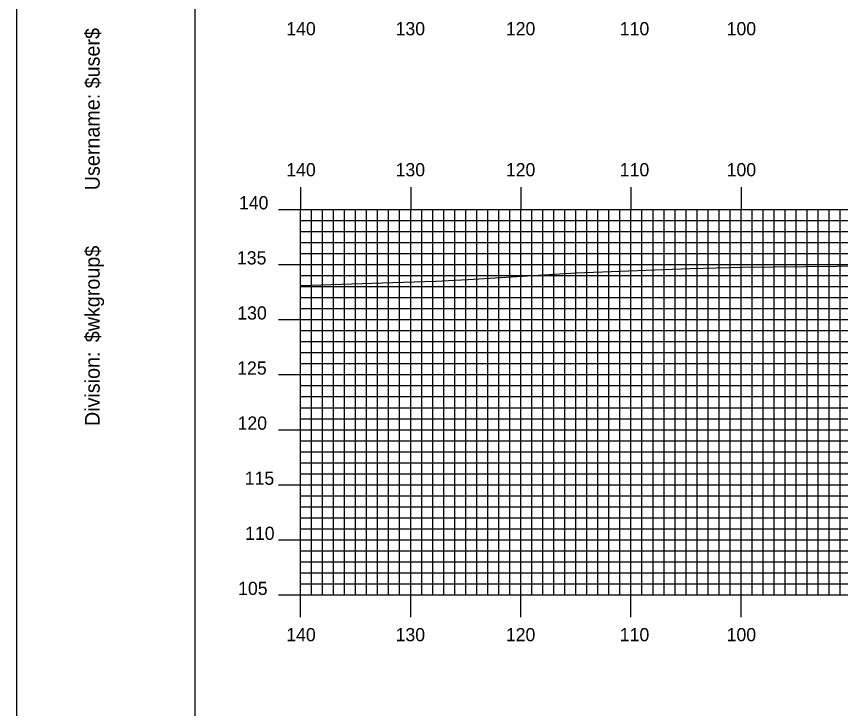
# Model space of a CAD drawing. Extents: x 1768087 to 1768430, y 442591 to 442811.
# Drawn here: x 1768087.2 to 1768162, y 442653.4 to 442716.2 of the extents above; entities that cross this region are included whole.
import ezdxf

# ---------------------------------------------------------------- set-up
doc = ezdxf.new("R2010")
doc.units = 0
for name, color, linetype in [('BORDER', 7, 'Continuous'), ('H_V ANNOTATION', 7, 'Continuous'), ('MAJOR', 7, 'Continuous'), ('MINOR', 7, 'Continuous'), ('PLOT BOUNDARY', 7, 'Continuous'), ('S_Roadway_Centerline', 7, 'Continuous')]:
    doc.layers.add(name, color=color, linetype=linetype)

msp = doc.modelspace()

# ---------------------------------------------------------------- linework, layer by layer
at = {"layer": 'BORDER'}
msp.add_lwpolyline([(1768103.363, 442596.665), (1768423.363, 442596.665), (1768423.363, 442806.665), (1768103.363, 442806.665)], close=True, dxfattribs=at)
at = {"layer": 'MAJOR'}
for p, q in [((1768112.963, 442700.669), (1768112.963, 442698.665)), ((1768122.963, 442700.669), (1768122.963, 442698.665)), ((1768132.963, 442700.669), (1768132.963, 442698.665)), ((1768142.963, 442700.669), (1768142.963, 442698.665)), ((1768152.963, 442700.669), (1768152.963, 442698.665)), ((1768110.959, 442698.665), (1768112.963, 442698.665)), ((1768112.963, 442698.665), (1768392.963, 442698.665)), ((1768112.963, 442663.665), (1768112.963, 442698.665)), ((1768112.963, 442663.665), (1768112.963, 442698.665)), ((1768112.963, 442698.665), (1768392.963, 442698.665)), ((1768122.963, 442663.665), (1768122.963, 442698.665)), ((1768132.963, 442663.665), (1768132.963, 442698.665)), ((1768142.963, 442663.665), (1768142.963, 442698.665)), ((1768152.963, 442663.665), (1768152.963, 442698.665)), ((1768110.959, 442693.665), (1768112.963, 442693.665)), ((1768112.963, 442693.665), (1768392.963, 442693.665)), ((1768110.959, 442688.665), (1768112.963, 442688.665)), ((1768112.963, 442688.665), (1768392.963, 442688.665)), ((1768110.959, 442683.665), (1768112.963, 442683.665)), ((1768112.963, 442683.665), (1768392.963, 442683.665)), ((1768110.959, 442678.665), (1768112.963, 442678.665)), ((1768112.963, 442678.665), (1768392.963, 442678.665)), ((1768110.959, 442673.665), (1768112.963, 442673.665)), ((1768112.963, 442673.665), (1768392.963, 442673.665)), ((1768110.959, 442668.665), (1768112.963, 442668.665)), ((1768112.963, 442668.665), (1768392.963, 442668.665)), ((1768110.959, 442663.665), (1768112.963, 442663.665)), ((1768112.963, 442663.665), (1768392.963, 442663.665)), ((1768112.963, 442663.665), (1768392.963, 442663.665)), ((1768112.963, 442661.661), (1768112.963, 442663.665)), ((1768122.963, 442661.661), (1768122.963, 442663.665)), ((1768132.963, 442661.661), (1768132.963, 442663.665)), ((1768142.963, 442661.661), (1768142.963, 442663.665)), ((1768152.963, 442661.661), (1768152.963, 442663.665))]:
    msp.add_line(p, q, dxfattribs=at)
at = {"layer": 'MINOR'}
for p, q in [((1768113.963, 442663.665), (1768113.963, 442698.665)), ((1768114.963, 442663.665), (1768114.963, 442698.665)), ((1768115.963, 442663.665), (1768115.963, 442698.665)), ((1768116.963, 442663.665), (1768116.963, 442698.665)), ((1768117.963, 442663.665), (1768117.963, 442698.665)), ((1768118.963, 442663.665), (1768118.963, 442698.665)), ((1768119.963, 442663.665), (1768119.963, 442698.665)), ((1768120.963, 442663.665), (1768120.963, 442698.665)), ((1768121.963, 442663.665), (1768121.963, 442698.665)), ((1768123.963, 442663.665), (1768123.963, 442698.665)), ((1768124.963, 442663.665), (1768124.963, 442698.665)), ((1768125.963, 442663.665), (1768125.963, 442698.665)), ((1768126.963, 442663.665), (1768126.963, 442698.665)), ((1768127.963, 442663.665), (1768127.963, 442698.665)), ((1768128.963, 442663.665), (1768128.963, 442698.665)), ((1768129.963, 442663.665), (1768129.963, 442698.665)), ((1768130.963, 442663.665), (1768130.963, 442698.665)), ((1768131.963, 442663.665), (1768131.963, 442698.665)), ((1768133.963, 442663.665), (1768133.963, 442698.665)), ((1768134.963, 442663.665), (1768134.963, 442698.665)), ((1768135.963, 442663.665), (1768135.963, 442698.665)), ((1768136.963, 442663.665), (1768136.963, 442698.665)), ((1768137.963, 442663.665), (1768137.963, 442698.665)), ((1768138.963, 442663.665), (1768138.963, 442698.665)), ((1768139.963, 442663.665), (1768139.963, 442698.665)), ((1768140.963, 442663.665), (1768140.963, 442698.665)), ((1768141.963, 442663.665), (1768141.963, 442698.665)), ((1768143.963, 442663.665), (1768143.963, 442698.665)), ((1768144.963, 442663.665), (1768144.963, 442698.665)), ((1768145.963, 442663.665), (1768145.963, 442698.665)), ((1768146.963, 442663.665), (1768146.963, 442698.665)), ((1768147.963, 442663.665), (1768147.963, 442698.665)), ((1768148.963, 442663.665), (1768148.963, 442698.665)), ((1768149.963, 442663.665), (1768149.963, 442698.665)), ((1768150.963, 442663.665), (1768150.963, 442698.665)), ((1768151.963, 442663.665), (1768151.963, 442698.665)), ((1768153.963, 442663.665), (1768153.963, 442698.665)), ((1768154.963, 442663.665), (1768154.963, 442698.665)), ((1768155.963, 442663.665), (1768155.963, 442698.665)), ((1768156.963, 442663.665), (1768156.963, 442698.665)), ((1768157.963, 442663.665), (1768157.963, 442698.665)), ((1768158.963, 442663.665), (1768158.963, 442698.665)), ((1768159.963, 442663.665), (1768159.963, 442698.665)), ((1768160.963, 442663.665), (1768160.963, 442698.665)), ((1768161.963, 442663.665), (1768161.963, 442698.665)), ((1768112.963, 442697.665), (1768392.963, 442697.665)), ((1768112.963, 442697.665), (1768114.967, 442697.665)), ((1768112.963, 442696.665), (1768392.963, 442696.665)), ((1768112.963, 442696.665), (1768114.967, 442696.665)), ((1768112.963, 442695.665), (1768392.963, 442695.665)), ((1768112.963, 442695.665), (1768114.967, 442695.665)), ((1768112.963, 442694.665), (1768392.963, 442694.665)), ((1768112.963, 442694.665), (1768114.967, 442694.665)), ((1768112.963, 442692.665), (1768392.963, 442692.665)), ((1768112.963, 442692.665), (1768114.967, 442692.665)), ((1768112.963, 442691.665), (1768392.963, 442691.665)), ((1768112.963, 442691.665), (1768114.967, 442691.665)), ((1768112.963, 442690.665), (1768392.963, 442690.665)), ((1768112.963, 442690.665), (1768114.967, 442690.665)), ((1768112.963, 442689.665), (1768392.963, 442689.665)), ((1768112.963, 442689.665), (1768114.967, 442689.665)), ((1768112.963, 442687.665), (1768392.963, 442687.665)), ((1768112.963, 442687.665), (1768114.967, 442687.665)), ((1768112.963, 442686.665), (1768392.963, 442686.665)), ((1768112.963, 442686.665), (1768114.967, 442686.665)), ((1768112.963, 442685.665), (1768392.963, 442685.665)), ((1768112.963, 442685.665), (1768114.967, 442685.665)), ((1768112.963, 442684.665), (1768392.963, 442684.665)), ((1768112.963, 442684.665), (1768114.967, 442684.665)), ((1768112.963, 442682.665), (1768392.963, 442682.665)), ((1768112.963, 442682.665), (1768114.967, 442682.665)), ((1768112.963, 442681.665), (1768392.963, 442681.665)), ((1768112.963, 442681.665), (1768114.967, 442681.665)), ((1768112.963, 442680.665), (1768392.963, 442680.665)), ((1768112.963, 442680.665), (1768114.967, 442680.665)), ((1768112.963, 442679.665), (1768392.963, 442679.665)), ((1768112.963, 442679.665), (1768114.967, 442679.665)), ((1768112.963, 442677.665), (1768392.963, 442677.665)), ((1768112.963, 442677.665), (1768114.967, 442677.665)), ((1768112.963, 442676.665), (1768392.963, 442676.665)), ((1768112.963, 442676.665), (1768114.967, 442676.665)), ((1768112.963, 442675.665), (1768392.963, 442675.665)), ((1768112.963, 442675.665), (1768114.967, 442675.665)), ((1768112.963, 442674.665), (1768392.963, 442674.665)), ((1768112.963, 442674.665), (1768114.967, 442674.665)), ((1768112.963, 442672.665), (1768392.963, 442672.665)), ((1768112.963, 442672.665), (1768114.967, 442672.665)), ((1768112.963, 442671.665), (1768392.963, 442671.665)), ((1768112.963, 442671.665), (1768114.967, 442671.665)), ((1768112.963, 442670.665), (1768392.963, 442670.665)), ((1768112.963, 442670.665), (1768114.967, 442670.665)), ((1768112.963, 442669.665), (1768392.963, 442669.665)), ((1768112.963, 442669.665), (1768114.967, 442669.665)), ((1768112.963, 442667.665), (1768392.963, 442667.665)), ((1768112.963, 442667.665), (1768114.967, 442667.665)), ((1768112.963, 442666.665), (1768392.963, 442666.665)), ((1768112.963, 442666.665), (1768114.967, 442666.665)), ((1768112.963, 442665.665), (1768392.963, 442665.665)), ((1768112.963, 442665.665), (1768114.967, 442665.665)), ((1768112.963, 442664.665), (1768392.963, 442664.665)), ((1768112.963, 442664.665), (1768114.967, 442664.665))]:
    msp.add_line(p, q, dxfattribs=at)
at = {"layer": 'PLOT BOUNDARY'}
msp.add_lwpolyline([(1768087.176, 442590.547), (1768427.176, 442590.547), (1768427.176, 442810.547), (1768087.176, 442810.547)], close=True, dxfattribs=at)
at = {"layer": 'S_Roadway_Centerline'}
msp.add_lwpolyline([(1768112.963, 442691.74), (1768121.34, 442692.014), (1768125.228, 442692.14), (1768128.174, 442692.308), (1768137.972, 442692.913), (1768148.318, 442693.303), (1768153.094, 442693.404), (1768167.33, 442693.572)], dxfattribs=at)

# ---------------------------------------------------------------- texts
at = {"layer": 'BORDER'}
for s, p in [('$user$', (1768094.732, 442709.648)), ('Username:', (1768094.732, 442700.401)), ('$wkgroup$', (1768094.732, 442686.604)), ('Division:', (1768094.732, 442678.997))]:
    msp.add_text(s, height=1.3392, rotation=90, dxfattribs=at).set_placement(p)
at = {"layer": 'H_V ANNOTATION'}
for s, p in [('140', (1768111.667, 442714.465)), ('130', (1768121.593, 442714.465)), ('120', (1768131.603, 442714.465)), ('110', (1768141.946, 442714.465)), ('100', (1768151.646, 442714.465)), ('140', (1768111.667, 442701.665)), ('130', (1768121.593, 442701.665)), ('120', (1768131.603, 442701.665)), ('110', (1768141.946, 442701.665)), ('100', (1768151.646, 442701.665)), ('140', (1768107.372, 442698.665)), ('135', (1768107.19, 442693.665)), ('130', (1768107.222, 442688.665)), ('125', (1768107.212, 442683.665)), ('120', (1768107.244, 442678.665)), ('115', (1768107.897, 442673.665)), ('110', (1768107.929, 442668.665)), ('105', (1768107.297, 442663.665)), ('140', (1768111.667, 442659.465)), ('130', (1768121.593, 442659.465)), ('120', (1768131.603, 442659.465)), ('110', (1768141.946, 442659.465)), ('100', (1768151.646, 442659.465))]:
    msp.add_text(s, height=1.2, dxfattribs=at).set_placement(p)
at = {"layer": 'MAJOR'}
msp.add_text('-', height=0.012, dxfattribs=at).set_placement((1768112.954, 442663.665))

doc.saveas('drawing.dxf')
